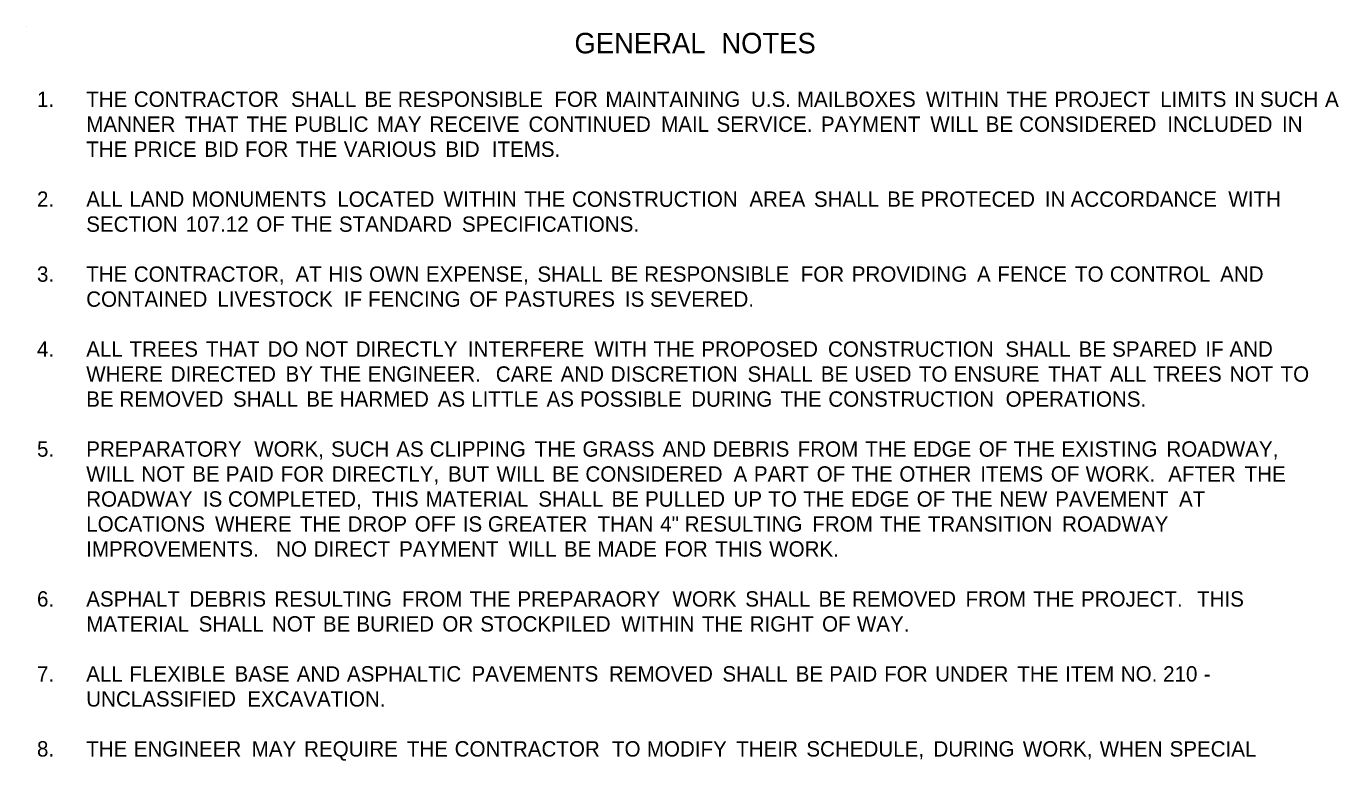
# Model space of a CAD drawing. Extents: x 1930579 to 1932218, y 596452 to 599494.
# Drawn here: x 1930760 to 1931323, y 599078 to 599394 of the extents above; entities that cross this region are included whole.
import ezdxf

# ---------------------------------------------------------------- set-up
doc = ezdxf.new("R2010")
doc.units = 0
doc.layers.add('Default', color=7, linetype='Continuous')
doc.layers.add('R_Border', color=7, linetype='Continuous')

msp = doc.modelspace()

# ---------------------------------------------------------------- linework, layer by layer
at = {"layer": 'R_Border'}
msp.add_line((1930759.59, 599393.53), (1930759.59, 599393.53), dxfattribs=at)

# ---------------------------------------------------------------- texts
at = {"layer": 'Default'}
for s, height, p in [('GENERAL', 8.8, (1930994.83, 599381.89)), (' NOTES', 8.8, (1931054.58, 599381.89)), ('1.', 6.6, (1930764.2, 599358.92)), ('THE', 6.6, (1930785.33, 599358.92)), (' CONTRACTOR', 6.6, (1930803.29, 599358.92)), (' SHALL', 6.6, (1930870.79, 599358.92)), (' BE', 6.6, (1930902.24, 599358.92)), (' RESPONSIBLE', 6.6, (1930916.61, 599358.92)), (' FOR', 6.6, (1930983.78, 599358.92)), (' MAINTAINING', 6.6, (1931005.68, 599358.92)), (' U.S.', 6.6, (1931068.12, 599358.92)), (' MAILBOXES', 6.6, (1931087.81, 599358.92)), (' WITHIN', 6.6, (1931143.19, 599358.92)), (' THE', 6.6, (1931177.77, 599358.92)), (' PROJECT', 6.6, (1931198.29, 599358.92)), (' LIMITS', 6.6, (1931243.71, 599358.92)), (' IN', 6.6, (1931275.5, 599358.92)), (' SUCH', 6.6, (1931286.53, 599358.92)), (' A', 6.6, (1931314.47, 599358.92)), ('MANNER', 6.6, (1930785.33, 599348.2)), (' THAT', 6.6, (1930825.17, 599348.2)), (' THE', 6.6, (1930851.63, 599348.2)), (' PUBLIC', 6.6, (1930872.14, 599348.2)), (' MAY', 6.6, (1930907.65, 599348.2)), (' RECEIVE', 6.6, (1930930.13, 599348.2)), (' CONTINUED', 6.6, (1930972.68, 599348.2)), (' MAIL', 6.6, (1931029.57, 599348.2)), (' SERVICE.', 6.6, (1931053.33, 599348.2)), (' PAYMENT', 6.6, (1931098.13, 599348.2)), (' WILL', 6.6, (1931145.09, 599348.2)), (' BE', 6.6, (1931168.84, 599348.2)), (' CONSIDERED', 6.6, (1931183.21, 599348.2)), (' INCLUDED', 6.6, (1931246.77, 599348.2)), (' IN', 6.6, (1931295.98, 599348.2)), ('THE', 6.6, (1930785.33, 599337.47)), (' PRICE', 6.6, (1930803.29, 599337.47)), (' BID', 6.6, (1930833.54, 599337.47)), (' FOR', 6.6, (1930850.98, 599337.47)), (' THE', 6.6, (1930872.88, 599337.47)), (' VARIOUS', 6.6, (1930893.4, 599337.47)), (' BID', 6.6, (1930936.99, 599337.47)), ('  ITEMS.', 6.6, (1930954.43, 599337.47)), ('2.', 6.6, (1930764.2, 599316.02)), ('ALL', 6.6, (1930785.33, 599316.02)), (' LAND', 6.6, (1930801.41, 599316.02)), (' MONUMENTS', 6.6, (1930828.08, 599316.02)), (' LOCATED', 6.6, (1930890.61, 599316.02)), (' WITHIN', 6.6, (1930936.24, 599316.02)), (' THE', 6.6, (1930970.82, 599316.02)), (' CONSTRUCTION', 6.6, (1930991.34, 599316.02)), (' AREA', 6.6, (1931067.43, 599316.02)), (' SHALL', 6.6, (1931095.13, 599316.02)), (' BE', 6.6, (1931126.58, 599316.02)), (' PROTECED', 6.6, (1931140.95, 599316.02)), (' IN', 6.6, (1931194.26, 599316.02)), (' ACCORDANCE', 6.6, (1931205.29, 599316.02)), (' WITH', 6.6, (1931272.95, 599316.02)), ('SECTION', 6.6, (1930785.33, 599305.3)), (' 107.12', 6.6, (1930825.57, 599305.3)), (' OF', 6.6, (1930855.84, 599305.3)), (' THE', 6.6, (1930870.78, 599305.3)), (' STANDARD', 6.6, (1930891.3, 599305.3)), (' SPECIFICATIONS.', 6.6, (1930944.1, 599305.3)), ('3.', 6.6, (1930764.2, 599283.85)), ('THE', 6.6, (1930785.33, 599283.85)), (' CONTRACTOR,', 6.6, (1930803.29, 599283.85)), (' AT', 6.6, (1930872.66, 599283.85)), (' HIS', 6.6, (1930886.82, 599283.85)), (' OWN', 6.6, (1930904.27, 599283.85)), (' EXPENSE,', 6.6, (1930928.61, 599283.85)), (' SHALL', 6.6, (1930976.49, 599283.85)), (' BE', 6.6, (1931007.94, 599283.85)), (' RESPONSIBLE', 6.6, (1931022.31, 599283.85)), (' FOR', 6.6, (1931089.47, 599283.85)), (' PROVIDING', 6.6, (1931111.37, 599283.85)), (' A', 6.6, (1931165.11, 599283.85)), (' FENCE', 6.6, (1931173.84, 599283.85)), (' TO', 6.6, (1931207.16, 599283.85)), (' CONTROL', 6.6, (1931222.12, 599283.85)), (' AND', 6.6, (1931269.44, 599283.85)), ('CONTAINED', 6.6, (1930785.33, 599273.12)), (' LIVESTOCK', 6.6, (1930839.15, 599273.12)), (' IF', 6.6, (1930893.46, 599273.12)), (' FENCING', 6.6, (1930903.79, 599273.12)), (' OF', 6.6, (1930947.27, 599273.12)), (' PASTURES', 6.6, (1930962.22, 599273.12)), (' IS', 6.6, (1931014.01, 599273.12)), (' SEVERED.', 6.6, (1931024.8, 599273.12)), ('4.', 6.6, (1930764.2, 599251.67)), ('ALL', 6.6, (1930785.33, 599251.67)), (' TREES', 6.6, (1930801.41, 599251.67)), (' THAT', 6.6, (1930834.24, 599251.67)), (' DO', 6.6, (1930860.69, 599251.67)), (' NOT', 6.6, (1930876.68, 599251.67)), (' DIRECTLY', 6.6, (1930898.52, 599251.67)), (' INTERFERE', 6.6, (1930946.62, 599251.67)), (' WITH', 6.6, (1931000.95, 599251.67)), (' THE', 6.6, (1931026.32, 599251.67)), (' PROPOSED', 6.6, (1931046.84, 599251.67)), (' CONSTRUCTION', 6.6, (1931101.18, 599251.67)), (' SHALL', 6.6, (1931177.28, 599251.67)), (' BE', 6.6, (1931208.73, 599251.67)), (' SPARED', 6.6, (1931223.1, 599251.67)), (' IF', 6.6, (1931263.1, 599251.67)), (' AND', 6.6, (1931273.43, 599251.67)), ('WHERE', 6.6, (1930785.33, 599240.95)), (' DIRECTED', 6.6, (1930819.17, 599240.95)), (' BY', 6.6, (1930868.38, 599240.95)), (' THE', 6.6, (1930883.17, 599240.95)), (' ENGINEER.', 6.6, (1930903.69, 599240.95)), ('  CARE', 6.6, (1930956.17, 599240.95)), (' AND', 6.6, (1930986.43, 599240.95)), (' DISCRETION', 6.6, (1931007.97, 599240.95)), (' SHALL', 6.6, (1931066.65, 599240.95)), (' BE', 6.6, (1931098.1, 599240.95)), (' USED', 6.6, (1931112.47, 599240.95)), (' TO', 6.6, (1931140.16, 599240.95)), (' ENSURE', 6.6, (1931155.12, 599240.95)), (' THAT', 6.6, (1931195.62, 599240.95)), (' ALL', 6.6, (1931222.08, 599240.95)), (' TREES', 6.6, (1931240.72, 599240.95)), (' NOT', 6.6, (1931273.55, 599240.95)), (' TO', 6.6, (1931295.39, 599240.95)), ('BE', 6.6, (1930785.33, 599230.22)), (' REMOVED', 6.6, (1930797.14, 599230.22)), (' SHALL', 6.6, (1930845.84, 599230.22)), (' BE', 6.6, (1930877.3, 599230.22)), (' HARMED', 6.6, (1930891.67, 599230.22)), (' AS', 6.6, (1930933.7, 599230.22)), (' LITTLE', 6.6, (1930948.08, 599230.22)), (' AS', 6.6, (1930980.39, 599230.22)), (' POSSIBLE', 6.6, (1930994.77, 599230.22)), (' DURING', 6.6, (1931042.46, 599230.22)), (' THE', 6.6, (1931080.81, 599230.22)), (' CONSTRUCTION', 6.6, (1931101.33, 599230.22)), (' OPERATIONS.', 6.6, (1931177.42, 599230.22)), ('5.', 6.6, (1930764.2, 599208.77)), ('PREPARATORY', 6.6, (1930785.33, 599208.77)), (' WORK,', 6.6, (1930854.97, 599208.77)), (' SUCH', 6.6, (1930887.96, 599208.77)), (' AS', 6.6, (1930915.9, 599208.77)), (' CLIPPING', 6.6, (1930930.29, 599208.77)), (' THE', 6.6, (1930975.31, 599208.77)), (' GRASS', 6.6, (1930995.83, 599208.77)), (' AND', 6.6, (1931030.2, 599208.77)), (' DEBRIS', 6.6, (1931051.74, 599208.77)), (' FROM', 6.6, (1931088.15, 599208.77)), (' THE', 6.6, (1931117.17, 599208.77)), (' EDGE', 6.6, (1931137.68, 599208.77)), (' OF', 6.6, (1931165.89, 599208.77)), (' THE', 6.6, (1931180.84, 599208.77)), (' EXISTING', 6.6, (1931201.35, 599208.77)), (' ROADWAY,', 6.6, (1931246.38, 599208.77)), ('WILL', 6.6, (1930785.33, 599198.05)), (' NOT', 6.6, (1930806.52, 599198.05)), (' BE', 6.6, (1930828.36, 599198.05)), (' PAID', 6.6, (1930842.74, 599198.05)), (' FOR', 6.6, (1930866.33, 599198.05)), (' DIRECTLY,', 6.6, (1930888.23, 599198.05)), (' BUT', 6.6, (1930938.14, 599198.05)), (' WILL', 6.6, (1930958.96, 599198.05)), (' BE', 6.6, (1930982.71, 599198.05)), (' CONSIDERED', 6.6, (1930997.08, 599198.05)), (' A', 6.6, (1931060.64, 599198.05)), (' PART', 6.6, (1931069.37, 599198.05)), (' OF', 6.6, (1931096.34, 599198.05)), (' THE', 6.6, (1931111.29, 599198.05)), (' OTHER', 6.6, (1931131.8, 599198.05)), (' ITEMS', 6.6, (1931166.52, 599198.05)), (' OF', 6.6, (1931196.78, 599198.05)), (' WORK.', 6.6, (1931211.72, 599198.05)), ('  AFTER', 6.6, (1931244.73, 599198.05)), (' THE', 6.6, (1931279.96, 599198.05)), ('ROADWAY', 6.6, (1930785.33, 599187.32)), (' IS', 6.6, (1930832.92, 599187.32)), (' COMPLETED,', 6.6, (1930843.71, 599187.32)), (' THIS', 6.6, (1930905.4, 599187.32)), (' MATERIAL', 6.6, (1930928.49, 599187.32)), (' SHALL', 6.6, (1930976.84, 599187.32)), (' BE', 6.6, (1931008.29, 599187.32)), (' PULLED', 6.6, (1931022.66, 599187.32)), (' UP', 6.6, (1931060.61, 599187.32)), (' TO', 6.6, (1931075.58, 599187.32)), (' THE', 6.6, (1931090.53, 599187.32)), (' EDGE', 6.6, (1931111.05, 599187.32)), (' OF', 6.6, (1931139.25, 599187.32)), (' THE', 6.6, (1931154.2, 599187.32)), (' NEW', 6.6, (1931174.71, 599187.32)), (' PAVEMENT', 6.6, (1931198.68, 599187.32)), (' AT', 6.6, (1931251.8, 599187.32)), ('LOCATIONS', 6.6, (1930785.33, 599176.6)), (' WHERE', 6.6, (1930838.14, 599176.6)), (' THE', 6.6, (1930874.54, 599176.6)), (' DROP', 6.6, (1930895.05, 599176.6)), (' OFF', 6.6, (1930923.86, 599176.6)), (' IS', 6.6, (1930944.44, 599176.6)), (' GREATER', 6.6, (1930955.23, 599176.6)), (' THAN', 6.6, (1931002.25, 599176.6)), (' 4"', 6.6, (1931029.16, 599176.6)), (' RESULTING', 6.6, (1931039.69, 599176.6)), (' FROM', 6.6, (1931094.45, 599176.6)), (' THE', 6.6, (1931123.47, 599176.6)), (' TRANSITION', 6.6, (1931143.98, 599176.6)), (' ROADWAY', 6.6, (1931201.64, 599176.6)), ('IMPROVEMENTS.', 6.6, (1930785.33, 599165.87)), ('  NO', 6.6, (1930861.9, 599165.87)), (' DIRECT', 6.6, (1930880.44, 599165.87)), (' PAYMENT', 6.6, (1930917.15, 599165.87)), (' WILL', 6.6, (1930964.11, 599165.87)), (' BE', 6.6, (1930987.86, 599165.87)), (' MADE', 6.6, (1931002.23, 599165.87)), (' FOR', 6.6, (1931030.94, 599165.87)), (' THIS', 6.6, (1931052.84, 599165.87)), (' WORK.', 6.6, (1931075.93, 599165.87)), ('6.', 6.6, (1930764.2, 599144.42)), ('ASPHALT', 6.6, (1930785.33, 599144.42)), (' DEBRIS', 6.6, (1930827.18, 599144.42)), (' RESULTING', 6.6, (1930863.59, 599144.42)), (' FROM', 6.6, (1930918.35, 599144.42)), (' THE', 6.6, (1930947.37, 599144.42)), (' PREPARAORY', 6.6, (1930967.88, 599144.42)), (' WORK', 6.6, (1931034.44, 599144.42)), (' SHALL', 6.6, (1931065.67, 599144.42)), (' BE', 6.6, (1931097.12, 599144.42)), (' REMOVED', 6.6, (1931111.49, 599144.42)), (' FROM', 6.6, (1931160.19, 599144.42)), (' THE', 6.6, (1931189.21, 599144.42)), (' PROJECT.', 6.6, (1931209.73, 599144.42)), ('  THIS', 6.6, (1931257.09, 599144.42)), ('MATERIAL', 6.6, (1930785.33, 599133.7)), (' SHALL', 6.6, (1930831.13, 599133.7)), (' NOT', 6.6, (1930862.58, 599133.7)), (' BE', 6.6, (1930884.42, 599133.7)), (' BURIED', 6.6, (1930898.79, 599133.7)), (' OR', 6.6, (1930935.7, 599133.7)), (' STOCKPILED', 6.6, (1930951.97, 599133.7)), (' WITHIN', 6.6, (1931012.46, 599133.7)), (' THE', 6.6, (1931047.05, 599133.7)), (' RIGHT', 6.6, (1931067.56, 599133.7)), (' OF', 6.6, (1931098.63, 599133.7)), (' WAY.', 6.6, (1931113.57, 599133.7)), (' BASE', 6.6, (1930846.53, 599112.25)), (' ASPHALTIC', 6.6, (1930894.75, 599112.25)), (' PAVEMENTS', 6.6, (1930948.2, 599112.25)), (' REMOVED', 6.6, (1931007.16, 599112.25)), (' SHALL', 6.6, (1931055.86, 599112.25)), (' FOR', 6.6, (1931125.28, 599112.25)), (' NO.', 6.6, (1931226.82, 599112.25)), (' 210', 6.6, (1931244.97, 599112.25)), ('7.', 6.6, (1930764.2, 599112.25)), ('ALL', 6.6, (1930785.33, 599112.25)), (' FLEXIBLE', 6.6, (1930801.41, 599112.25)), (' AND', 6.6, (1930873.21, 599112.25)), (' BE', 6.6, (1931087.31, 599112.25)), (' PAID', 6.6, (1931101.69, 599112.25)), (' UNDER', 6.6, (1931147.18, 599112.25)), (' THE', 6.6, (1931182.41, 599112.25)), (' ITEM', 6.6, (1931202.92, 599112.25)), (' -', 6.6, (1931262.46, 599112.25)), ('UNCLASSIFIED', 6.6, (1930785.33, 599101.52)), (' EXCAVATION.', 6.6, (1930851.97, 599101.52)), ('8.', 6.6, (1930764.2, 599080.07)), ('THE', 6.6, (1930785.33, 599080.07)), (' ENGINEER', 6.6, (1930803.29, 599080.07)), (' MAY', 6.6, (1930853.89, 599080.07)), (' REQUIRE', 6.6, (1930876.37, 599080.07)), (' THE', 6.6, (1930920.46, 599080.07)), (' CONTRACTOR', 6.6, (1930940.97, 599080.07)), (' TO', 6.6, (1931008.48, 599080.07)), (' MODIFY', 6.6, (1931023.43, 599080.07)), (' THEIR', 6.6, (1931061.78, 599080.07)), (' SCHEDULE,', 6.6, (1931091.89, 599080.07)), (' DURING', 6.6, (1931146.41, 599080.07)), (' WORK,', 6.6, (1931184.77, 599080.07)), (' WHEN', 6.6, (1931217.76, 599080.07)), (' SPECIAL', 6.6, (1931247.74, 599080.07))]:
    msp.add_text(s, height=height, dxfattribs=at).set_placement(p)

doc.saveas('drawing.dxf')
